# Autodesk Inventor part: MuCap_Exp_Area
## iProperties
Shininess: 64.0
Length Units: 11269
Angle Units: 11279
Time Units: 11290
Mass Units: 11283
Length Display Precision: 3
Angle Display Precision: 2
Compacted: True
Part Number: MuCap_Exp_Area
Document SubType Name: Modeling
Created: 2004-08
Designer: John Blackburn
Manufacturer: Standard
Standards Organization: Custom
Density: 0.0
Volumn: 0.0
Area: 0.0
PropertySet Name: Model Information
Control State: 0
Master: False
Checked Out: False
Author: John Blackburn
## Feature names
1. Extrusion1
2. Extrusion2
3. Extrusion3
